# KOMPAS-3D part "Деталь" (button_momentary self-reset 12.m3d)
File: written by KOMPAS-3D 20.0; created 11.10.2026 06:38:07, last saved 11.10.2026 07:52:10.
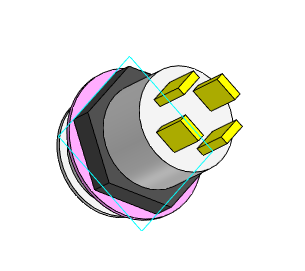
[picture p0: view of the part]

Document properties: Полное имя файла: D:\myProjects\Progect_esp32\box_compas\button_momentary self-reset 12.m3d

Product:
- Part/product: Деталь
    Масса: 0.0186527

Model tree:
1. Эскиз:1
2. Элемент выдавливания:1
     Расстояние 1 = 3
3. Фаска:1  (with: Элемент выдавливания:1)
     Угол = 45; Длина 1 = 2.5; Длина 2 = 2.5
4. Эскиз:2  (with: Элемент выдавливания:1)
5. Элемент выдавливания:2
     Расстояние 1 = 1
6. Эскиз:3  (with: Элемент выдавливания:1)
7. Элемент выдавливания:3
     Расстояние 1 = 15
8. Смещенная плоскость:1  (with: Элемент выдавливания:1)
     Расстояние = 4.5
9. Эскиз:4
10. Элемент выдавливания:4
     Расстояние 1 = 3
11. Эскиз:5  (with: Элемент выдавливания:3)
12. Элемент выдавливания:5
     Расстояние 1 = 5
13. Массив по концентрической сетке:1  (with: Элемент выдавливания:5, Эскиз:5, Элемент выдавливания:3)  (4 pattern instances)
     Шаг 2 = 360
14. Эскиз:6  (with: Элемент выдавливания:3)
15. Элемент выдавливания:6
     Расстояние 1 = 0.5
